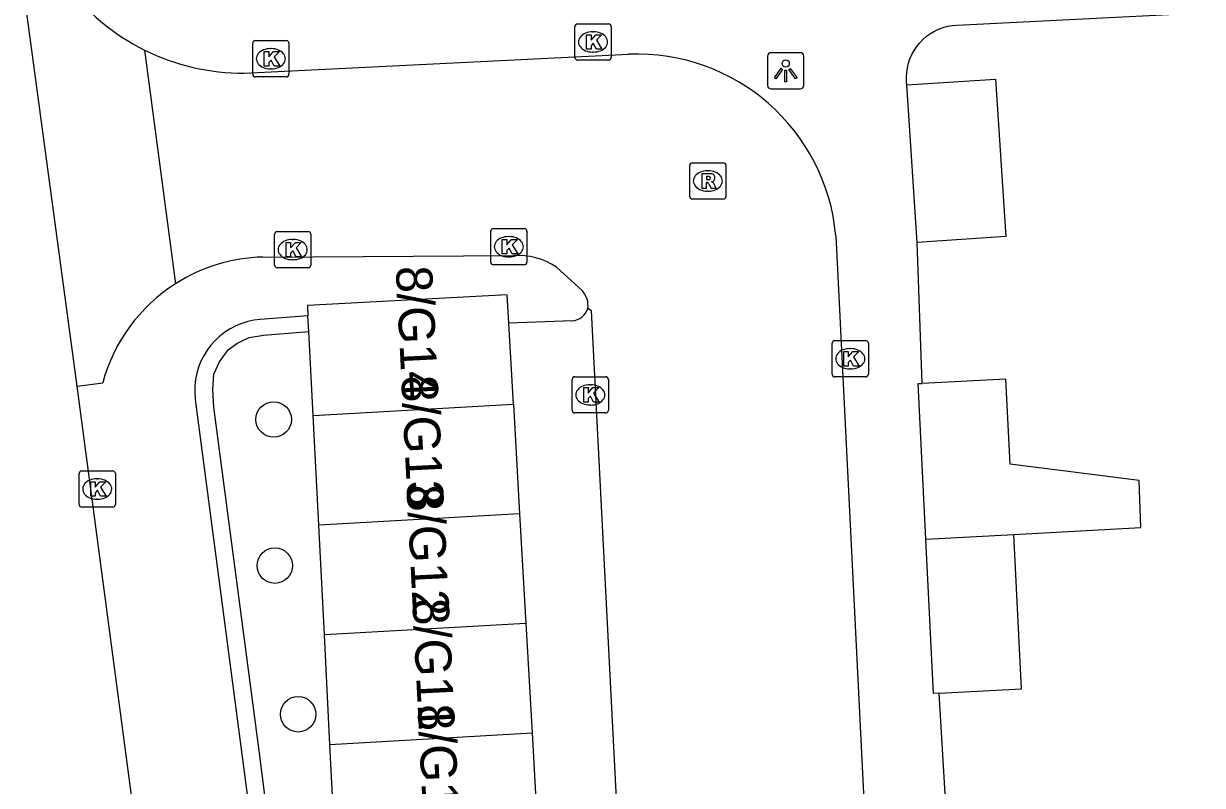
# Model space of a CAD drawing. Extents: x 161084 to 161928, y 385355 to 386522.
# Drawn here: x 161313.02 to 161345.53, y 385517.23 to 385538.24 of the extents above; entities that cross this region are included whole.
import ezdxf

# ---------------------------------------------------------------- set-up
doc = ezdxf.new("R2010")
doc.units = 0
for name, color, linetype in [('IMGEO_Boom', 7, 'Continuous'), ('IMGEO_Haag', 7, 'Continuous'), ('IMGEO_Kolk', 7, 'Continuous'), ('IMGEO_Lichtpunt', 7, 'Continuous'), ('IMGEO_Pand', 7, 'Continuous'), ('IMGEO_Pand_nummerreeks', 7, 'Continuous'), ('IMGEO_Rijbaan_lokaal_open', 7, 'Continuous'), ('IMGEO_Rioolput', 7, 'Continuous'), ('IMGEO_Voetpad_open', 7, 'Continuous')]:
    doc.layers.add(name, color=color, linetype=linetype)

msp = doc.modelspace()

# ---------------------------------------------------------------- linework, layer by layer
at = {"layer": 'IMGEO_Boom'}
for centre in [(161319.916, 385527.324), (161319.947, 385523.292), (161320.591, 385519.191)]:
    msp.add_circle(centre, 0.489, dxfattribs=at)
at = {"layer": 'IMGEO_Haag'}
msp.add_lwpolyline([(161322.343, 385495.966), (161319.524, 385518.117), (161318.264, 385527.665), (161318.24, 385528.146), (161318.264, 385528.577), (161318.422, 385528.916), (161318.662, 385529.24), (161318.903, 385529.422), (161319.069, 385529.505), (161319.244, 385529.58), (161319.633, 385529.65), (161320.885, 385529.754)], dxfattribs=at)
at = {"layer": 'IMGEO_Kolk'}
for p, q in [((161328.225, 385537.311), (161328.225, 385538.163)), ((161328.3, 385538.237), (161329.152, 385538.237)), ((161329.226, 385538.163), (161329.226, 385537.311)), ((161319.413, 385537.773), (161320.265, 385537.773)), ((161328.713, 385538.017), (161328.738, 385538.017)), ((161319.338, 385536.847), (161319.338, 385537.699)), ((161319.826, 385537.553), (161319.851, 385537.553)), ((161320.339, 385537.699), (161320.339, 385536.847)), ((161328.736, 385537.457), (161328.711, 385537.457)), ((161329.152, 385537.237), (161328.3, 385537.237)), ((161319.849, 385536.993), (161319.824, 385536.993)), ((161320.265, 385536.773), (161319.413, 385536.773)), ((161325.977, 385532.588), (161326.829, 385532.588)), ((161319.941, 385531.583), (161319.941, 385532.435)), ((161320.016, 385532.509), (161320.868, 385532.509)), ((161320.429, 385532.289), (161320.454, 385532.289)), ((161320.942, 385532.435), (161320.942, 385531.583)), ((161325.902, 385531.662), (161325.902, 385532.514)), ((161326.39, 385532.368), (161326.415, 385532.368)), ((161326.903, 385532.514), (161326.903, 385531.662)), ((161320.452, 385531.729), (161320.427, 385531.729)), ((161326.413, 385531.808), (161326.388, 385531.808)), ((161320.868, 385531.509), (161320.016, 385531.509)), ((161326.829, 385531.588), (161325.977, 385531.588)), ((161335.32, 385528.572), (161335.32, 385529.424)), ((161335.395, 385529.498), (161336.247, 385529.498)), ((161336.321, 385529.424), (161336.321, 385528.572)), ((161335.808, 385529.278), (161335.833, 385529.278)), ((161335.831, 385528.718), (161335.806, 385528.718)), ((161328.149, 385527.576), (161328.149, 385528.428)), ((161328.224, 385528.502), (161329.076, 385528.502)), ((161329.15, 385528.428), (161329.15, 385527.576)), ((161336.247, 385528.498), (161335.395, 385528.498)), ((161328.637, 385528.282), (161328.662, 385528.282)), ((161328.66, 385527.722), (161328.635, 385527.722)), ((161329.076, 385527.502), (161328.224, 385527.502)), ((161314.55, 385524.979), (161314.55, 385525.831)), ((161314.625, 385525.905), (161315.477, 385525.905)), ((161315.551, 385525.831), (161315.551, 385524.979)), ((161315.038, 385525.685), (161315.063, 385525.685)), ((161315.061, 385525.125), (161315.036, 385525.125)), ((161315.477, 385524.905), (161314.625, 385524.905))]:
    msp.add_line(p, q, dxfattribs=at)
for points in [[(161328.225, 385537.311), (161328.225, 385538.163)], [(161328.3, 385538.237), (161329.152, 385538.237)], [(161329.226, 385538.163), (161329.226, 385537.311)], [(161319.413, 385537.773), (161320.265, 385537.773)], [(161328.546, 385537.937), (161328.669, 385537.937), (161328.669, 385537.786), (161328.799, 385537.937), (161328.963, 385537.937), (161328.817, 385537.786), (161328.97, 385537.537), (161328.818, 385537.537), (161328.733, 385537.701), (161328.669, 385537.634), (161328.669, 385537.537), (161328.546, 385537.537), (161328.546, 385537.937)], [(161319.338, 385536.847), (161319.338, 385537.699)], [(161319.659, 385537.473), (161319.782, 385537.473), (161319.782, 385537.322), (161319.912, 385537.473), (161320.076, 385537.473), (161319.93, 385537.322), (161320.083, 385537.073), (161319.931, 385537.073), (161319.846, 385537.237), (161319.782, 385537.17), (161319.782, 385537.073), (161319.659, 385537.073), (161319.659, 385537.473)], [(161320.339, 385537.699), (161320.339, 385536.847)], [(161329.152, 385537.237), (161328.3, 385537.237)], [(161320.265, 385536.773), (161319.413, 385536.773)], [(161325.977, 385532.588), (161326.829, 385532.588)], [(161319.941, 385531.583), (161319.941, 385532.435)], [(161320.016, 385532.509), (161320.868, 385532.509)], [(161320.942, 385532.435), (161320.942, 385531.583)], [(161325.902, 385531.662), (161325.902, 385532.514)], [(161326.223, 385532.288), (161326.346, 385532.288), (161326.346, 385532.137), (161326.476, 385532.288), (161326.64, 385532.288), (161326.494, 385532.137), (161326.647, 385531.888), (161326.495, 385531.888), (161326.41, 385532.052), (161326.346, 385531.985), (161326.346, 385531.888), (161326.223, 385531.888), (161326.223, 385532.288)], [(161326.903, 385532.514), (161326.903, 385531.662)], [(161320.262, 385532.209), (161320.385, 385532.209), (161320.385, 385532.058), (161320.515, 385532.209), (161320.679, 385532.209), (161320.533, 385532.058), (161320.686, 385531.809), (161320.534, 385531.809), (161320.449, 385531.973), (161320.385, 385531.906), (161320.385, 385531.809), (161320.262, 385531.809), (161320.262, 385532.209)], [(161320.868, 385531.509), (161320.016, 385531.509)], [(161326.829, 385531.588), (161325.977, 385531.588)], [(161335.32, 385528.572), (161335.32, 385529.424)], [(161335.395, 385529.498), (161336.247, 385529.498)], [(161336.321, 385529.424), (161336.321, 385528.572)], [(161335.641, 385529.198), (161335.764, 385529.198), (161335.764, 385529.047), (161335.894, 385529.198), (161336.058, 385529.198), (161335.912, 385529.047), (161336.065, 385528.798), (161335.913, 385528.798), (161335.828, 385528.962), (161335.764, 385528.895), (161335.764, 385528.798), (161335.641, 385528.798), (161335.641, 385529.198)], [(161328.149, 385527.576), (161328.149, 385528.428)], [(161328.224, 385528.502), (161329.076, 385528.502)], [(161329.15, 385528.428), (161329.15, 385527.576)], [(161336.247, 385528.498), (161335.395, 385528.498)], [(161328.47, 385528.202), (161328.593, 385528.202), (161328.593, 385528.051), (161328.723, 385528.202), (161328.887, 385528.202), (161328.741, 385528.051), (161328.894, 385527.802), (161328.742, 385527.802), (161328.657, 385527.966), (161328.593, 385527.899), (161328.593, 385527.802), (161328.47, 385527.802), (161328.47, 385528.202)], [(161329.076, 385527.502), (161328.224, 385527.502)], [(161314.55, 385524.979), (161314.55, 385525.831)], [(161314.625, 385525.905), (161315.477, 385525.905)], [(161315.551, 385525.831), (161315.551, 385524.979)], [(161314.871, 385525.605), (161314.994, 385525.605), (161314.994, 385525.454), (161315.124, 385525.605), (161315.288, 385525.605), (161315.142, 385525.454), (161315.295, 385525.205), (161315.143, 385525.205), (161315.058, 385525.369), (161314.994, 385525.302), (161314.994, 385525.205), (161314.871, 385525.205), (161314.871, 385525.605)], [(161315.477, 385524.905), (161314.625, 385524.905)]]:
    msp.add_lwpolyline(points, dxfattribs=at)
for centre, start, end in [((161328.302, 385538.161), 91.552, 178.448), ((161328.302, 385538.161), 91.552, 178.448), ((161329.15, 385538.161), 1.552, 88.448), ((161329.15, 385538.161), 1.552, 88.448), ((161319.415, 385537.697), 91.552, 178.448), ((161319.415, 385537.697), 91.552, 178.448), ((161320.263, 385537.697), 1.552, 88.448), ((161320.263, 385537.697), 1.552, 88.448), ((161328.302, 385537.313), 181.552, 268.448), ((161328.302, 385537.313), 181.552, 268.448), ((161329.15, 385537.313), 271.552, 358.448), ((161329.15, 385537.313), 271.552, 358.448), ((161319.415, 385536.849), 181.552, 268.448), ((161319.415, 385536.849), 181.552, 268.448), ((161320.263, 385536.849), 271.552, 358.448), ((161320.263, 385536.849), 271.552, 358.448), ((161325.979, 385532.512), 91.552, 178.448), ((161325.979, 385532.512), 91.552, 178.448), ((161326.827, 385532.512), 1.552, 88.448), ((161326.827, 385532.512), 1.552, 88.448), ((161320.018, 385532.433), 91.552, 178.448), ((161320.018, 385532.433), 91.552, 178.448), ((161320.866, 385532.433), 1.552, 88.448), ((161320.866, 385532.433), 1.552, 88.448), ((161325.979, 385531.664), 181.552, 268.448), ((161325.979, 385531.664), 181.552, 268.448), ((161326.827, 385531.664), 271.552, 358.448), ((161326.827, 385531.664), 271.552, 358.448), ((161320.018, 385531.585), 181.552, 268.448), ((161320.018, 385531.585), 181.552, 268.448), ((161320.866, 385531.585), 271.552, 358.448), ((161320.866, 385531.585), 271.552, 358.448), ((161335.397, 385529.422), 91.552, 178.448), ((161335.397, 385529.422), 91.552, 178.448), ((161336.245, 385529.422), 1.552, 88.448), ((161336.245, 385529.422), 1.552, 88.448), ((161328.226, 385528.426), 91.552, 178.448), ((161328.226, 385528.426), 91.552, 178.448), ((161329.074, 385528.426), 1.552, 88.448), ((161329.074, 385528.426), 1.552, 88.448), ((161335.397, 385528.574), 181.552, 268.448), ((161335.397, 385528.574), 181.552, 268.448), ((161336.245, 385528.574), 271.552, 358.448), ((161336.245, 385528.574), 271.552, 358.448), ((161328.226, 385527.578), 181.552, 268.448), ((161328.226, 385527.578), 181.552, 268.448), ((161329.074, 385527.578), 271.552, 358.448), ((161329.074, 385527.578), 271.552, 358.448), ((161314.627, 385525.829), 91.552, 178.448), ((161314.627, 385525.829), 91.552, 178.448), ((161315.475, 385525.829), 1.552, 88.448), ((161315.475, 385525.829), 1.552, 88.448), ((161314.627, 385524.981), 181.552, 268.448), ((161314.627, 385524.981), 181.552, 268.448), ((161315.475, 385524.981), 271.552, 358.448), ((161315.475, 385524.981), 271.552, 358.448)]:
    msp.add_arc(centre, 0.0765, start, end, dxfattribs=at)
for centre, major_axis, ratio, start_param, end_param in [((161328.712, 385537.737), (-0.387, 0.002), 0.722429, 4.712389, 7.853982), ((161328.737, 385537.737), (-0.39, 0.002), 0.717154, 1.570796, 4.712389), ((161319.825, 385537.273), (-0.387, 0.002), 0.722429, 4.712389, 7.853982), ((161319.85, 385537.273), (-0.39, 0.002), 0.717154, 1.570796, 4.712389), ((161320.428, 385532.009), (-0.387, 0.002), 0.722429, 4.712389, 7.853982), ((161320.453, 385532.009), (-0.39, 0.002), 0.717154, 1.570796, 4.712389), ((161326.389, 385532.088), (-0.387, 0.002), 0.722429, 4.712389, 7.853982), ((161326.414, 385532.088), (-0.39, 0.002), 0.717154, 1.570796, 4.712389), ((161335.807, 385528.998), (-0.387, 0.002), 0.722429, 4.712389, 7.853982), ((161335.832, 385528.998), (-0.39, 0.002), 0.717154, 1.570796, 4.712389), ((161328.636, 385528.002), (-0.387, 0.002), 0.722429, 4.712389, 7.853982), ((161328.661, 385528.002), (-0.39, 0.002), 0.717154, 1.570796, 4.712389), ((161315.037, 385525.405), (-0.387, 0.002), 0.722429, 4.712389, 7.853982), ((161315.062, 385525.405), (-0.39, 0.002), 0.717154, 1.570796, 4.712389)]:
    msp.add_ellipse(centre, major_axis=major_axis, ratio=ratio, start_param=start_param, end_param=end_param, dxfattribs=at)
at = {"layer": 'IMGEO_Lichtpunt'}
for p, q in [((161333.54, 385537.345), (161333.54, 385536.538)), ((161333.54, 385537.345), (161333.54, 385536.538)), ((161334.442, 385537.44), (161333.634, 385537.44)), ((161334.442, 385537.44), (161333.634, 385537.44)), ((161334.536, 385536.538), (161334.536, 385537.345)), ((161334.536, 385536.538), (161334.536, 385537.345)), ((161333.634, 385536.444), (161334.442, 385536.444)), ((161333.634, 385536.444), (161334.442, 385536.444))]:
    msp.add_line(p, q, dxfattribs=at)
for points in [[(161333.914, 385537.009), (161333.953, 385536.981), (161333.765, 385536.719), (161333.727, 385536.746), (161333.914, 385537.009)], [(161334.016, 385536.961), (161334.063, 385536.961), (161334.063, 385536.639), (161334.016, 385536.639), (161334.016, 385536.961)], [(161334.126, 385536.981), (161334.164, 385537.008), (161334.351, 385536.746), (161334.312, 385536.718), (161334.126, 385536.981)]]:
    msp.add_lwpolyline(points, dxfattribs=at)
msp.add_circle((161334.039, 385537.143), 0.0994, dxfattribs=at)
for centre, start, end in [((161333.634, 385537.345), 90, 180), ((161333.634, 385537.345), 90, 180), ((161334.442, 385537.345), 0, 90), ((161334.442, 385537.345), 0, 90), ((161333.634, 385536.538), 180, 270), ((161333.634, 385536.538), 180, 270), ((161334.442, 385536.538), 270, 0), ((161334.442, 385536.538), 270, 360)]:
    msp.add_arc(centre, 0.0946, start, end, dxfattribs=at)
at = {"layer": 'IMGEO_Pand'}
for points in [[(161337.384, 385536.554), (161339.827, 385536.714), (161340.11, 385532.366), (161337.667, 385532.206)], [(161337.667, 385532.206), (161337.384, 385536.554)], [(161326.404, 385529.981), (161326.359, 385530.765), (161320.848, 385530.47), (161320.863, 385530.18)], [(161320.885, 385529.754), (161320.863, 385530.18)], [(161326.53, 385527.743), (161326.404, 385529.981)], [(161321.004, 385527.431), (161320.885, 385529.754)], [(161340.328, 385524.152), (161343.829, 385524.345), (161343.791, 385525.64), (161340.231, 385526.092), (161340.114, 385528.439), (161337.807, 385528.319)], [(161337.905, 385524.018), (161337.691, 385528.313), (161337.807, 385528.319)], [(161321.004, 385527.431), (161326.53, 385527.743)], [(161326.53, 385527.743), (161326.701, 385524.721)], [(161321.16, 385524.408), (161321.004, 385527.431)], [(161326.701, 385524.721), (161321.16, 385524.408)], [(161326.701, 385524.721), (161326.871, 385521.699)], [(161321.315, 385521.385), (161321.16, 385524.408)], [(161337.905, 385524.018), (161340.328, 385524.152)], [(161338.275, 385519.773), (161340.54, 385519.891), (161340.328, 385524.152)], [(161338.275, 385519.773), (161338.117, 385519.765), (161337.905, 385524.018)], [(161326.871, 385521.699), (161321.315, 385521.385)], [(161326.871, 385521.699), (161327.042, 385518.677)], [(161321.47, 385518.362), (161321.315, 385521.385)], [(161321.47, 385518.362), (161327.042, 385518.677)], [(161327.042, 385518.677), (161327.213, 385515.655)], [(161321.626, 385515.339), (161321.47, 385518.362)]]:
    msp.add_lwpolyline(points, dxfattribs=at)
at = {"layer": 'IMGEO_Rijbaan_lokaal_open'}
for points in [[(161314.499, 385528.244), (161313.019, 385539.216)], [(161316.356, 385537.511), (161317.208, 385531.066)], [(161319.103, 385536.877), (161329.708, 385537.397)], [(161335.42, 385532.391), (161337.024, 385500.143), (161337.796, 385485.654)], [(161319.618, 385531.804), (161326.533, 385531.849)], [(161327.718, 385531.525), (161328.43, 385530.869)], [(161330.768, 385487.413), (161330.865, 385487.775), (161328.687, 385530.316), (161328.582, 385530.386)], [(161314.499, 385528.244), (161315.202, 385528.336)], [(161317.934, 385502.34), (161314.499, 385528.244)]]:
    msp.add_lwpolyline(points, dxfattribs=at)
for centre, radius, start, end in [((161319.073, 385542.982), 6.108, 216.4587, 243.5922), ((161319.069, 385542.998), 6.121, 243.6895, 270.3182), ((161329.939, 385531.899), 5.503, 5.1264, 92.4109), ((161319.734, 385527.122), 4.683, 91.4164, 122.6353), ((161326.635, 385529.894), 1.957, 56.4198, 92.9963), ((161319.734, 385527.108), 4.695, 122.5428, 164.8404), ((161328.005, 385530.47), 0.583, 351.7507, 43.1869)]:
    msp.add_arc(centre, radius, start, end, dxfattribs=at)
at = {"layer": 'IMGEO_Rioolput'}
for p, q in [((161331.391, 385533.476), (161331.391, 385534.328)), ((161331.466, 385534.402), (161332.318, 385534.402)), ((161332.392, 385534.328), (161332.392, 385533.476)), ((161331.879, 385534.182), (161331.904, 385534.182)), ((161331.902, 385533.622), (161331.877, 385533.622)), ((161332.318, 385533.402), (161331.466, 385533.402))]:
    msp.add_line(p, q, dxfattribs=at)
for points in [[(161331.391, 385533.476), (161331.391, 385534.328)], [(161331.466, 385534.402), (161332.318, 385534.402)], [(161332.392, 385534.328), (161332.392, 385533.476)], [(161331.98, 385534.1), (161331.728, 385534.102), (161331.728, 385533.702)], [(161331.906, 385534.021), (161331.852, 385534.021), (161331.852, 385533.94)], [(161331.852, 385533.94), (161331.904, 385533.94)], [(161331.728, 385533.702), (161331.852, 385533.702), (161331.852, 385533.864), (161331.863, 385533.864)], [(161331.91, 385533.835), (161331.981, 385533.702), (161332.121, 385533.702), (161332.056, 385533.828)], [(161332.318, 385533.402), (161331.466, 385533.402)]]:
    msp.add_lwpolyline(points, dxfattribs=at)
for centre, radius, start, end in [((161331.468, 385534.326), 0.0765, 91.552, 178.448), ((161331.468, 385534.326), 0.0765, 91.552, 178.448), ((161332.316, 385534.326), 0.0765, 1.552, 88.448), ((161332.316, 385534.326), 0.0765, 1.552, 88.448), ((161331.888, 385534.129), 0.19, 274.7715, 282.9687), ((161331.912, 385533.925), 0.0964, 77.0061, 93.1865), ((161331.926, 385533.982), 0.0378, 276.6634, 79.6772), ((161331.979, 385533.99), 0.109, 350.3612, 89.416), ((161331.977, 385533.99), 0.112, 277.5842, 350.9817), ((161331.961, 385533.775), 0.108, 29.5134, 73.7905), ((161331.862, 385533.811), 0.0533, 26.0293, 88.6989), ((161331.468, 385533.478), 0.0765, 181.552, 268.448), ((161331.468, 385533.478), 0.0765, 181.552, 268.448), ((161332.316, 385533.478), 0.0765, 271.552, 358.448), ((161332.316, 385533.478), 0.0765, 271.552, 358.448)]:
    msp.add_arc(centre, radius, start, end, dxfattribs=at)
for centre, major_axis, ratio, start_param, end_param in [((161331.878, 385533.902), (-0.387, 0.002), 0.722429, 4.712389, 7.853982), ((161331.903, 385533.902), (-0.39, 0.002), 0.717154, 1.570796, 4.712389)]:
    msp.add_ellipse(centre, major_axis=major_axis, ratio=ratio, start_param=start_param, end_param=end_param, dxfattribs=at)
at = {"layer": 'IMGEO_Voetpad_open'}
for points in [[(161337.384, 385536.554), (161337.375, 385536.634), (161337.37, 385536.763), (161337.377, 385536.893), (161337.396, 385537.022), (161337.425, 385537.148), (161337.466, 385537.271), (161337.518, 385537.39), (161337.58, 385537.504), (161337.653, 385537.612), (161337.734, 385537.713), (161337.824, 385537.807), (161337.922, 385537.892), (161338.028, 385537.968), (161338.14, 385538.034), (161338.257, 385538.09), (161338.379, 385538.135), (161338.504, 385538.169), (161338.632, 385538.192), (161338.761, 385538.203), (161357.953, 385539.174)], [(161337.807, 385528.319), (161337.667, 385532.206)], [(161320.863, 385530.18), (161319.548, 385530.08), (161319.374, 385530.059), (161319.203, 385530.022), (161319.035, 385529.97), (161318.873, 385529.904), (161318.717, 385529.823), (161318.57, 385529.729), (161318.431, 385529.622), (161318.302, 385529.503), (161318.185, 385529.372), (161318.08, 385529.232), (161317.987, 385529.083), (161317.908, 385528.927), (161317.844, 385528.764), (161317.794, 385528.596), (161317.76, 385528.424), (161317.741, 385528.25), (161317.738, 385528.074), (161317.75, 385527.899), (161317.753, 385527.877), (161321.42, 385500), (161321.949, 385495.98), (161322.343, 385495.966)], [(161328.15, 385530.045), (161326.404, 385529.981)], [(161338.469, 385516.526), (161338.275, 385519.773)]]:
    msp.add_lwpolyline(points, dxfattribs=at)
msp.add_arc((161328.113, 385530.536), 0.493, 274.3428, 342.229, dxfattribs=at)

# ---------------------------------------------------------------- texts
at = {"layer": 'IMGEO_Pand_nummerreeks'}
for s, rotation, p in [('8/G14', 272.8588, (161323.282, 385531.539)), ('8/G13', 272.8562, (161323.433, 385528.519)), ('8/G12', 272.8562, (161323.583, 385525.505)), ('8/G11', 272.8562, (161323.74, 385522.368)), ('8/G10', 272.8562, (161323.885, 385519.455))]:
    msp.add_text(s, height=1, rotation=rotation, dxfattribs=at).set_placement(p)

doc.saveas('drawing.dxf')
